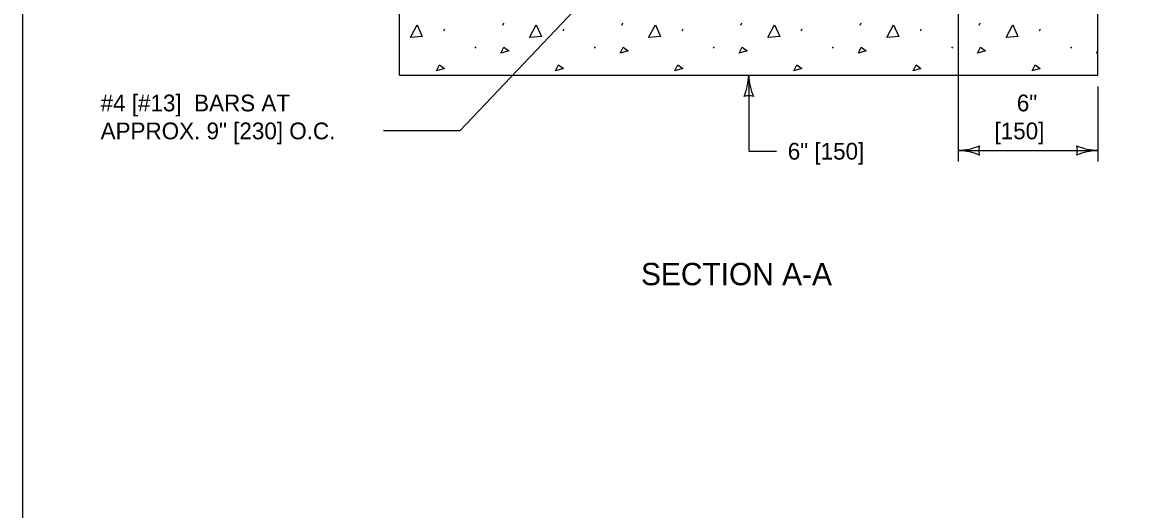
# Model space of a CAD drawing. Extents: x 49991.4 to 50021, y 49987.6 to 50011.4.
# Drawn here: x 50000.336 to 50004.383, y 50006.11 to 50007.853 of the extents above; entities that cross this region are included whole.
import ezdxf

# ---------------------------------------------------------------- set-up
doc = ezdxf.new("R2010")
doc.units = 0
for name, color, linetype in [('Level 1', 7, 'Continuous'), ('Level 2', 7, 'Continuous'), ('Level 3', 7, 'Continuous')]:
    doc.layers.add(name, color=color, linetype=linetype)

msp = doc.modelspace()

# ---------------------------------------------------------------- linework, layer by layer
at = {"layer": 'Level 1'}
for p, q in [((50001.6843, 50007.6648), (50001.6843, 50009.5741)), ((50004.1843, 50007.6648), (50004.1843, 50009.5745)), ((50002.0537, 50007.844), (50002.0573, 50007.852)), ((50002.4801, 50007.844), (50002.4836, 50007.852)), ((50002.9065, 50007.844), (50002.91, 50007.852)), ((50003.3328, 50007.844), (50003.3364, 50007.852)), ((50003.7592, 50007.844), (50003.7628, 50007.852)), ((50001.8433, 50007.8236), (50001.8468, 50007.8316)), ((50002.2696, 50007.8236), (50002.2732, 50007.8316)), ((50002.696, 50007.8236), (50002.6996, 50007.8316)), ((50003.1224, 50007.8236), (50003.1259, 50007.8316)), ((50003.5488, 50007.8236), (50003.5523, 50007.8316)), ((50003.9751, 50007.8236), (50003.9787, 50007.8316)), ((50001.9543, 50007.7668), (50001.9578, 50007.7614)), ((50002.3806, 50007.7668), (50002.3842, 50007.7614)), ((50002.807, 50007.7668), (50002.8106, 50007.7614)), ((50003.2334, 50007.7668), (50003.2369, 50007.7614)), ((50003.6598, 50007.7668), (50003.6633, 50007.7614)), ((50004.0861, 50007.7668), (50004.0897, 50007.7614)), ((50001.6843, 50007.6648), (50004.1843, 50007.6648))]:
    msp.add_line(p, q, dxfattribs=at)
msp.add_lwpolyline([(50008.6146, 50011.2628), (50000.3356, 50011.2628), (50000.3356, 50000.0624), (50008.6146, 50000.0624)], close=True, dxfattribs=at)
for points in [[(50001.7234, 50007.7996), (50001.7474, 50007.8449), (50001.766, 50007.8032), (50001.7243, 50007.7996)], [(50002.1498, 50007.7996), (50002.1737, 50007.8449), (50002.1924, 50007.8032), (50002.1506, 50007.7996)], [(50002.5761, 50007.7996), (50002.6001, 50007.8449), (50002.6188, 50007.8032), (50002.577, 50007.7996)], [(50003.0025, 50007.7996), (50003.0265, 50007.8449), (50003.0451, 50007.8032), (50003.0034, 50007.7996)], [(50003.4289, 50007.7996), (50003.4529, 50007.8449), (50003.4715, 50007.8032), (50003.4298, 50007.7996)], [(50003.8553, 50007.7996), (50003.8792, 50007.8449), (50003.8979, 50007.8032), (50003.8561, 50007.7996)], [(50002.0475, 50007.7437), (50002.0582, 50007.7659), (50002.0759, 50007.7525), (50002.0475, 50007.7437)], [(50002.4739, 50007.7437), (50002.4845, 50007.7659), (50002.5023, 50007.7525), (50002.4739, 50007.7437)], [(50002.9003, 50007.7437), (50002.9109, 50007.7659), (50002.9287, 50007.7525), (50002.9003, 50007.7437)], [(50003.3266, 50007.7437), (50003.3373, 50007.7659), (50003.355, 50007.7525), (50003.3266, 50007.7437)], [(50003.753, 50007.7437), (50003.7637, 50007.7659), (50003.7814, 50007.7525), (50003.753, 50007.7437)], [(50004.1794, 50007.7437), (50004.1843, 50007.754)], [(50004.1843, 50007.7452), (50004.1794, 50007.7437)], [(50001.8168, 50007.6802), (50001.8275, 50007.7024), (50001.8452, 50007.6891), (50001.8168, 50007.6802)], [(50002.2432, 50007.6802), (50002.2538, 50007.7024), (50002.2716, 50007.6891), (50002.2432, 50007.6802)], [(50002.6695, 50007.6802), (50002.6802, 50007.7024), (50002.698, 50007.6891), (50002.6695, 50007.6802)], [(50003.0959, 50007.6802), (50003.1066, 50007.7024), (50003.1243, 50007.6891), (50003.0959, 50007.6802)], [(50003.5223, 50007.6802), (50003.533, 50007.7024), (50003.5507, 50007.6891), (50003.5223, 50007.6802)], [(50003.9487, 50007.6802), (50003.9593, 50007.7024), (50003.9771, 50007.6891), (50003.9487, 50007.6802)]]:
    msp.add_lwpolyline(points, dxfattribs=at)
at = {"layer": 'Level 3'}
for p, q in [((50003.6843, 50008.8148), (50003.6841, 50007.3555)), ((50002.3329, 50007.9214), (50001.8998, 50007.4655)), ((50002.9343, 50007.6648), (50002.9343, 50007.3927)), ((50004.1841, 50007.6248), (50004.1841, 50007.3555)), ((50001.8998, 50007.4655), (50001.6276, 50007.4655)), ((50002.9343, 50007.3927), (50003.034, 50007.3927)), ((50003.6841, 50007.3955), (50004.1841, 50007.3955))]:
    msp.add_line(p, q, dxfattribs=at)
for centre, radius, start, end in [((50002.7122, 50007.674), 0.2223, 337.456, 357.6395), ((50003.167, 50007.6763), 0.233, 182.8273, 202.0772), ((50002.9343, 50007.5366), 0.0548, 72.1388, 107.8612), ((50003.6726, 50007.6282), 0.233, 272.8273, 292.0772), ((50003.8123, 50007.3955), 0.0548, 162.1388, 197.8612), ((50004.1933, 50007.6177), 0.2223, 247.456, 267.6395), ((50004.0559, 50007.3955), 0.0548, 342.1388, 17.8612), ((50003.675, 50007.1734), 0.2223, 67.456, 87.6395), ((50004.1956, 50007.1628), 0.233, 92.8273, 112.0772)]:
    msp.add_arc(centre, radius, start, end, dxfattribs=at)

# ---------------------------------------------------------------- texts
at = {"layer": 'Level 2'}
for s, height, p in [('#4 [#13]  BARS AT', 0.06, (50000.6148, 50007.5355)), ('6"', 0.06, (50003.8938, 50007.5355)), ('APPROX. 9" [230] O.C.', 0.06, (50000.6148, 50007.4355)), ('[150]', 0.06, (50003.8139, 50007.4355)), ('6" [150]', 0.06, (50003.074, 50007.3627)), ('SECTION A-A', 0.08, (50002.5487, 50006.913))]:
    msp.add_text(s, height=height, dxfattribs=at).set_placement(p)

doc.saveas('drawing.dxf')
